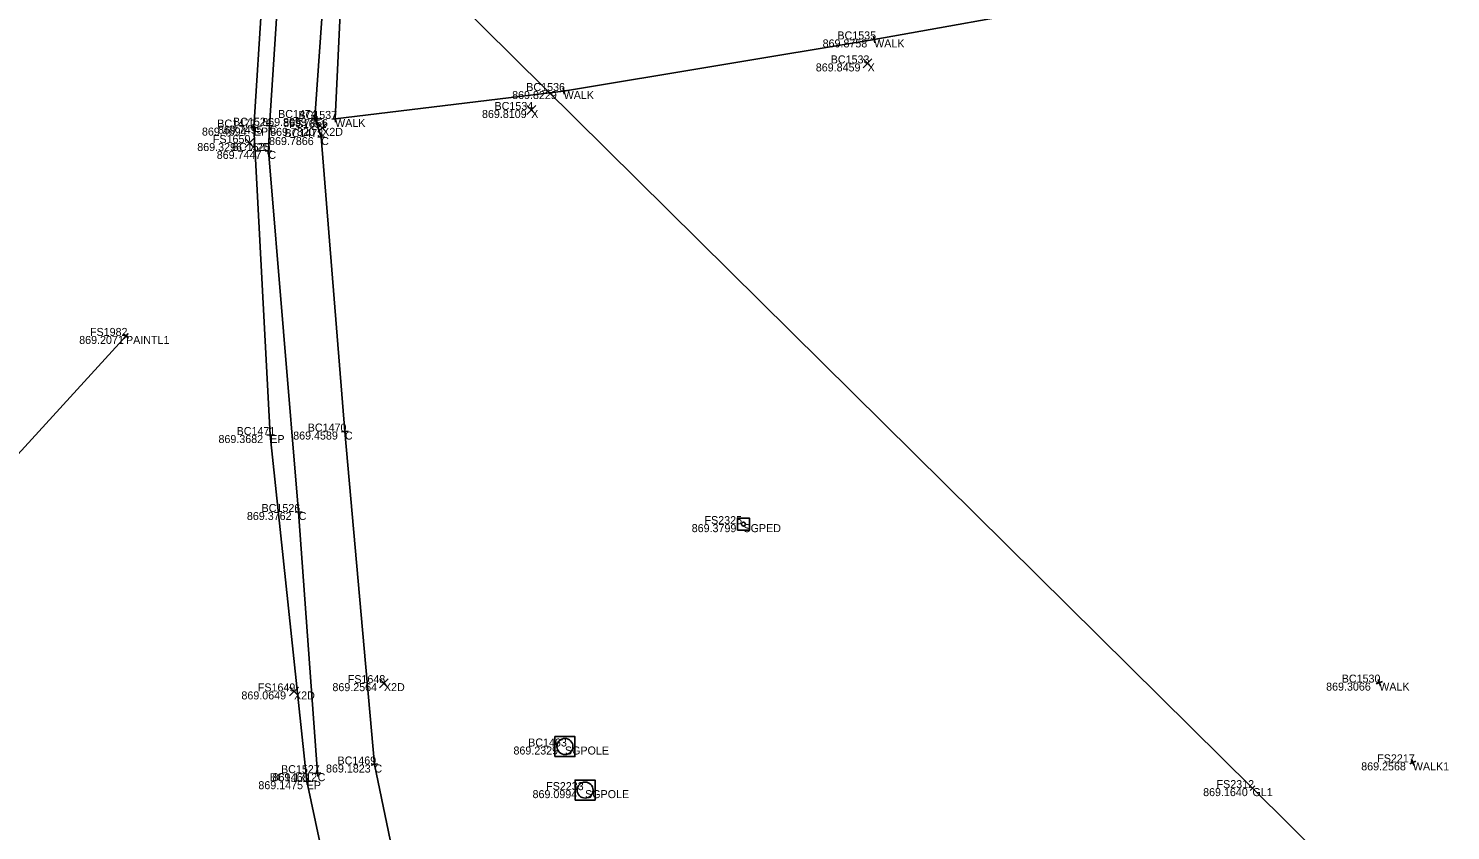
# Model space of a CAD drawing. Extents: x 1479425 to 1480294, y 379351 to 380102.
# Drawn here: x 1479693.48 to 1479704.14, y 379906.38 to 379912.39 of the extents above; entities that cross this region are included whole.
import ezdxf

# ---------------------------------------------------------------- set-up
doc = ezdxf.new("R2010")
doc.units = 0
for name, color, linetype in [('PM_X_Crosswalk', 7, 'Continuous'), ('PV_X_Curb', 7, 'Continuous'), ('PV_X_Walk', 7, 'Continuous'), ('SG_X_Poles', 7, 'Continuous'), ('SV_X_Random_Point', 7, 'Continuous'), ('SV_X_Shot_Marker', 7, 'Continuous'), ('SV_X_Text_Comment', 7, 'Continuous'), ('SV_X_Text_Elevation', 7, 'Continuous'), ('SV_X_Text_Name', 7, 'Continuous'), ('UT_X_Gas', 7, 'Continuous')]:
    doc.layers.add(name, color=color, linetype=linetype)

msp = doc.modelspace()

# ---------------------------------------------------------------- linework, layer by layer
at = {"layer": 'PM_X_Crosswalk'}
msp.add_lwpolyline([(1479656.672, 379868.951), (1479694.216, 379910.084)], dxfattribs=at)
at = {"layer": 'PV_X_Curb'}
for points in [[(1479696.264, 379903.539), (1479695.57, 379906.746), (1479695.297, 379909.341), (1479695.174, 379911.646), (1479695.365, 379914.612), (1479695.698, 379917.667), (1479696.262, 379919.569), (1479696.976, 379921.561), (1479698.108, 379924.214), (1479700.28, 379927.501), (1479703.025, 379930.637), (1479705.95, 379933.539), (1479706.943, 379934.379), (1479708.075, 379934.808), (1479711.183, 379937.553), (1479719.99, 379942.117), (1479736.739, 379950.532), (1479753.296, 379958.795), (1479766.716, 379965.563), (1479785.836, 379974.829), (1479802.25, 379983.054), (1479831.407, 379997.252)], [(1479714.562, 379931.597), (1479714.954, 379931.846), (1479713.923, 379933.146), (1479712.281, 379934.169), (1479710.424, 379934.773), (1479708.769, 379934.79), (1479708.11, 379934.798), (1479707.065, 379934.215), (1479706.4, 379933.843), (1479705.682, 379933.059), (1479703.005, 379930.335), (1479700.421, 379927.502), (1479698.116, 379923.793), (1479697.054, 379921.447), (1479696.317, 379919.513), (1479695.811, 379917.681), (1479695.461, 379914.266), (1479695.292, 379911.66), (1479695.283, 379911.471), (1479695.51, 379908.764), (1479695.652, 379906.806)], [(1479696.734, 379903.723), (1479696.078, 379906.871), (1479695.857, 379909.367), (1479695.679, 379911.575), (1479695.63, 379911.718), (1479695.729, 379913.104), (1479695.978, 379915.675), (1479696.198, 379917.494), (1479696.642, 379919.385), (1479697.412, 379921.373), (1479698.591, 379923.939), (1479699.838, 379926.058), (1479700.67, 379927.184), (1479703.372, 379930.269), (1479706.251, 379933.059), (1479706.672, 379933.535), (1479707.045, 379933.739), (1479707.413, 379933.924), (1479708.304, 379934.333), (1479710.149, 379934.374), (1479711.615, 379933.931), (1479713.621, 379932.885), (1479714.299, 379932.035), (1479714.562, 379931.597)]]:
    msp.add_lwpolyline(points, dxfattribs=at)
at = {"layer": 'PV_X_Walk'}
msp.add_lwpolyline([(1479701.835, 379912.5), (1479701.251, 379912.561), (1479699.823, 379912.307), (1479697.496, 379911.92), (1479695.783, 379911.711), (1479695.871, 379913.555), (1479696.025, 379915.67), (1479696.33, 379917.443), (1479698.253, 379916.872), (1479698.311, 379916.97), (1479698.916, 379918.91), (1479698.892, 379918.972), (1479699.457, 379920.649), (1479699.502, 379920.763), (1479697.529, 379921.382), (1479698.428, 379923.292)], dxfattribs=at)
at = {"layer": 'SG_X_Poles'}
for points in [[(1479698.799, 379908.628), (1479698.889, 379908.628), (1479698.889, 379908.718), (1479698.799, 379908.718)], [(1479697.431, 379906.931), (1479697.581, 379906.931), (1479697.581, 379907.081), (1479697.431, 379907.081)], [(1479697.582, 379906.604), (1479697.732, 379906.604), (1479697.732, 379906.754), (1479697.582, 379906.754)]]:
    msp.add_lwpolyline(points, close=True, dxfattribs=at)
for centre, radius in [((1479698.844, 379908.673), 0.015), ((1479697.506, 379907.006), 0.06), ((1479697.657, 379906.679), 0.06)]:
    msp.add_circle(centre, radius, dxfattribs=at)
at = {"layer": 'SV_X_Random_Point'}
for p, q in [((1479699.74, 379912.094), (1479699.807, 379912.161)), ((1479699.74, 379912.161), (1479699.807, 379912.094)), ((1479697.22, 379911.745), (1479697.287, 379911.811)), ((1479697.22, 379911.811), (1479697.287, 379911.745)), ((1479695.653, 379911.611), (1479695.719, 379911.677)), ((1479695.653, 379911.677), (1479695.719, 379911.611)), ((1479695.109, 379911.497), (1479695.175, 379911.564)), ((1479695.109, 379911.564), (1479695.175, 379911.497)), ((1479695.442, 379907.385), (1479695.508, 379907.452)), ((1479695.442, 379907.452), (1479695.508, 379907.385)), ((1479696.116, 379907.447), (1479696.182, 379907.514)), ((1479696.116, 379907.514), (1479696.182, 379907.447))]:
    msp.add_line(p, q, dxfattribs=at)
at = {"layer": 'SV_X_Shot_Marker'}
for p, q in [((1479699.848, 379912.311), (1479699.799, 379912.302)), ((1479699.828, 379912.282), (1479699.819, 379912.331)), ((1479699.823, 379912.307), (1479699.823, 379912.307)), ((1479697.521, 379911.925), (1479697.471, 379911.916)), ((1479697.5, 379911.896), (1479697.492, 379911.945)), ((1479697.496, 379911.92), (1479697.496, 379911.92)), ((1479695.606, 379911.71), (1479695.654, 379911.726)), ((1479695.638, 379911.694), (1479695.622, 379911.741)), ((1479695.63, 379911.718), (1479695.63, 379911.718)), ((1479695.808, 379911.714), (1479695.759, 379911.708)), ((1479695.786, 379911.687), (1479695.78, 379911.736)), ((1479695.783, 379911.711), (1479695.783, 379911.711)), ((1479695.149, 379911.647), (1479695.199, 379911.644)), ((1479695.172, 379911.621), (1479695.175, 379911.671)), ((1479695.174, 379911.646), (1479695.174, 379911.646)), ((1479695.317, 379911.659), (1479695.267, 379911.662)), ((1479695.294, 379911.685), (1479695.29, 379911.635)), ((1479695.292, 379911.66), (1479695.292, 379911.66)), ((1479695.284, 379911.496), (1479695.281, 379911.446)), ((1479695.654, 379911.573), (1479695.704, 379911.577)), ((1479695.681, 379911.55), (1479695.677, 379911.6)), ((1479695.679, 379911.575), (1479695.679, 379911.575)), ((1479695.308, 379911.47), (1479695.258, 379911.472)), ((1479695.283, 379911.471), (1479695.283, 379911.471)), ((1479694.198, 379910.101), (1479694.234, 379910.067)), ((1479694.199, 379910.065), (1479694.233, 379910.102)), ((1479694.216, 379910.084), (1479694.216, 379910.084)), ((1479695.299, 379909.316), (1479695.296, 379909.366)), ((1479695.832, 379909.365), (1479695.882, 379909.369)), ((1479695.859, 379909.342), (1479695.855, 379909.392)), ((1479695.857, 379909.367), (1479695.857, 379909.367)), ((1479695.272, 379909.34), (1479695.322, 379909.343)), ((1479695.297, 379909.341), (1479695.297, 379909.341)), ((1479695.535, 379908.766), (1479695.485, 379908.762)), ((1479695.508, 379908.789), (1479695.512, 379908.739)), ((1479695.51, 379908.764), (1479695.51, 379908.764)), ((1479703.586, 379907.476), (1479703.633, 379907.493)), ((1479703.618, 379907.461), (1479703.601, 379907.508)), ((1479703.609, 379907.485), (1479703.609, 379907.485)), ((1479695.677, 379906.808), (1479695.627, 379906.804)), ((1479695.65, 379906.831), (1479695.654, 379906.781)), ((1479695.652, 379906.806), (1479695.652, 379906.806)), ((1479696.053, 379906.866), (1479696.102, 379906.876)), ((1479696.083, 379906.847), (1479696.073, 379906.895)), ((1479696.078, 379906.871), (1479696.078, 379906.871)), ((1479703.884, 379906.896), (1479703.838, 379906.877)), ((1479703.851, 379906.91), (1479703.871, 379906.864)), ((1479703.861, 379906.887), (1479703.861, 379906.887)), ((1479695.546, 379906.744), (1479695.595, 379906.749)), ((1479695.573, 379906.721), (1479695.568, 379906.771)), ((1479695.57, 379906.746), (1479695.57, 379906.746)), ((1479702.677, 379906.712), (1479702.641, 379906.677)), ((1479702.641, 379906.712), (1479702.677, 379906.677)), ((1479702.659, 379906.694), (1479702.659, 379906.694))]:
    msp.add_line(p, q, dxfattribs=at)
at = {"layer": 'UT_X_Gas'}
msp.add_lwpolyline([(1479667.444, 379946.572), (1479666.862, 379942.802), (1479667.538, 379940.507), (1479675.403, 379934.504), (1479682.743, 379926.326), (1479692.421, 379916.824), (1479702.659, 379906.694), (1479713.881, 379895.567), (1479724.225, 379885.781), (1479733.117, 379877.795), (1479742.697, 379869.326), (1479754.816, 379857.131), (1479762.869, 379849.318), (1479772.436, 379840.641), (1479780.346, 379832.715), (1479784.901, 379828.191), (1479795.906, 379818.324), (1479806.128, 379806.719), (1479816.671, 379794.927)], dxfattribs=at)

# ---------------------------------------------------------------- texts
at = {"layer": 'SV_X_Text_Comment'}
for s, p in [('WALK', (1479699.823, 379912.247)), ('X', (1479699.774, 379912.067)), ('WALK', (1479697.496, 379911.86)), ('C', (1479695.63, 379911.658)), ('WALK', (1479695.783, 379911.651)), ('X', (1479697.253, 379911.718)), ('EP', (1479695.174, 379911.586)), ('C', (1479695.292, 379911.6)), ('X2D', (1479695.686, 379911.584)), ('X2D', (1479695.142, 379911.47)), ('C', (1479695.679, 379911.515)), ('C', (1479695.283, 379911.411)), ('PAINTL1', (1479694.216, 379910.024)), ('C', (1479695.857, 379909.307)), ('EP', (1479695.297, 379909.281)), ('C', (1479695.51, 379908.704)), ('SGPED', (1479698.844, 379908.613)), ('X2D', (1479696.149, 379907.421)), ('WALK', (1479703.609, 379907.425)), ('X2D', (1479695.475, 379907.359)), ('SGPOLE', (1479697.506, 379906.946)), ('C', (1479695.652, 379906.746)), ('C', (1479696.078, 379906.811)), ('WALK1', (1479703.861, 379906.827)), ('EP', (1479695.57, 379906.686)), ('SGPOLE', (1479697.657, 379906.619)), ('GL1', (1479702.659, 379906.634))]:
    msp.add_text(s, height=0.06, dxfattribs=at).set_placement(p)
at = {"layer": 'SV_X_Text_Elevation'}
for s, p in [('869.8758', (1479699.437, 379912.247)), ('869.8459', (1479699.386, 379912.067)), ('869.8229', (1479697.11, 379911.86)), ('869.8059', (1479695.237, 379911.658)), ('869.7856', (1479695.394, 379911.651)), ('869.8109', (1479696.884, 379911.718)), ('869.4694', (1479694.785, 379911.586)), ('869.7495', (1479694.905, 379911.6)), ('869.7820', (1479695.296, 379911.584)), ('869.3296', (1479694.75, 379911.47)), ('869.7866', (1479695.288, 379911.515)), ('869.7447', (1479694.896, 379911.411)), ('869.2071', (1479693.865, 379910.024)), ('869.4589', (1479695.469, 379909.307)), ('869.3682', (1479694.909, 379909.281)), ('869.3762', (1479695.122, 379908.704)), ('869.3799', (1479698.456, 379908.613)), ('869.2564', (1479695.763, 379907.421)), ('869.3066', (1479703.211, 379907.425)), ('869.0649', (1479695.081, 379907.359)), ('869.2329', (1479697.12, 379906.946)), ('869.1712', (1479695.314, 379906.746)), ('869.1823', (1479695.715, 379906.811)), ('869.2568', (1479703.474, 379906.827)), ('869.1475', (1479695.208, 379906.686)), ('869.0994', (1479697.263, 379906.619)), ('869.1640', (1479702.289, 379906.634))]:
    msp.add_text(s, height=0.06, dxfattribs=at).set_placement(p)
at = {"layer": 'SV_X_Text_Name'}
for s, p in [('BC1535', (1479699.548, 379912.307)), ('BC1533', (1479699.498, 379912.127)), ('BC1536', (1479697.216, 379911.92)), ('BC1534', (1479696.978, 379911.778)), ('BC1524', (1479695.018, 379911.66)), ('BC1474', (1479695.356, 379911.718)), ('BC1537', (1479695.508, 379911.711)), ('BC1472', (1479694.9, 379911.646)), ('BC1473', (1479695.404, 379911.575)), ('FS1651', (1479695.438, 379911.644)), ('FS1650', (1479694.867, 379911.53)), ('BC1525', (1479695.009, 379911.471)), ('FS1982', (1479693.946, 379910.084)), ('BC1471', (1479695.045, 379909.341)), ('BC1470', (1479695.578, 379909.367)), ('BC1526', (1479695.232, 379908.764)), ('FS2325', (1479698.552, 379908.673)), ('FS1649', (1479695.204, 379907.419)), ('FS1648', (1479695.878, 379907.481)), ('BC1530', (1479703.328, 379907.485)), ('BC1463', (1479697.23, 379907.006)), ('BC1469', (1479695.801, 379906.871)), ('FS2217', (1479703.594, 379906.887)), ('BC1468', (1479695.294, 379906.746)), ('BC1527', (1479695.378, 379906.806)), ('FS2233', (1479697.365, 379906.679)), ('FS2312', (1479702.39, 379906.694))]:
    msp.add_text(s, height=0.06, dxfattribs=at).set_placement(p)

doc.saveas('drawing.dxf')
